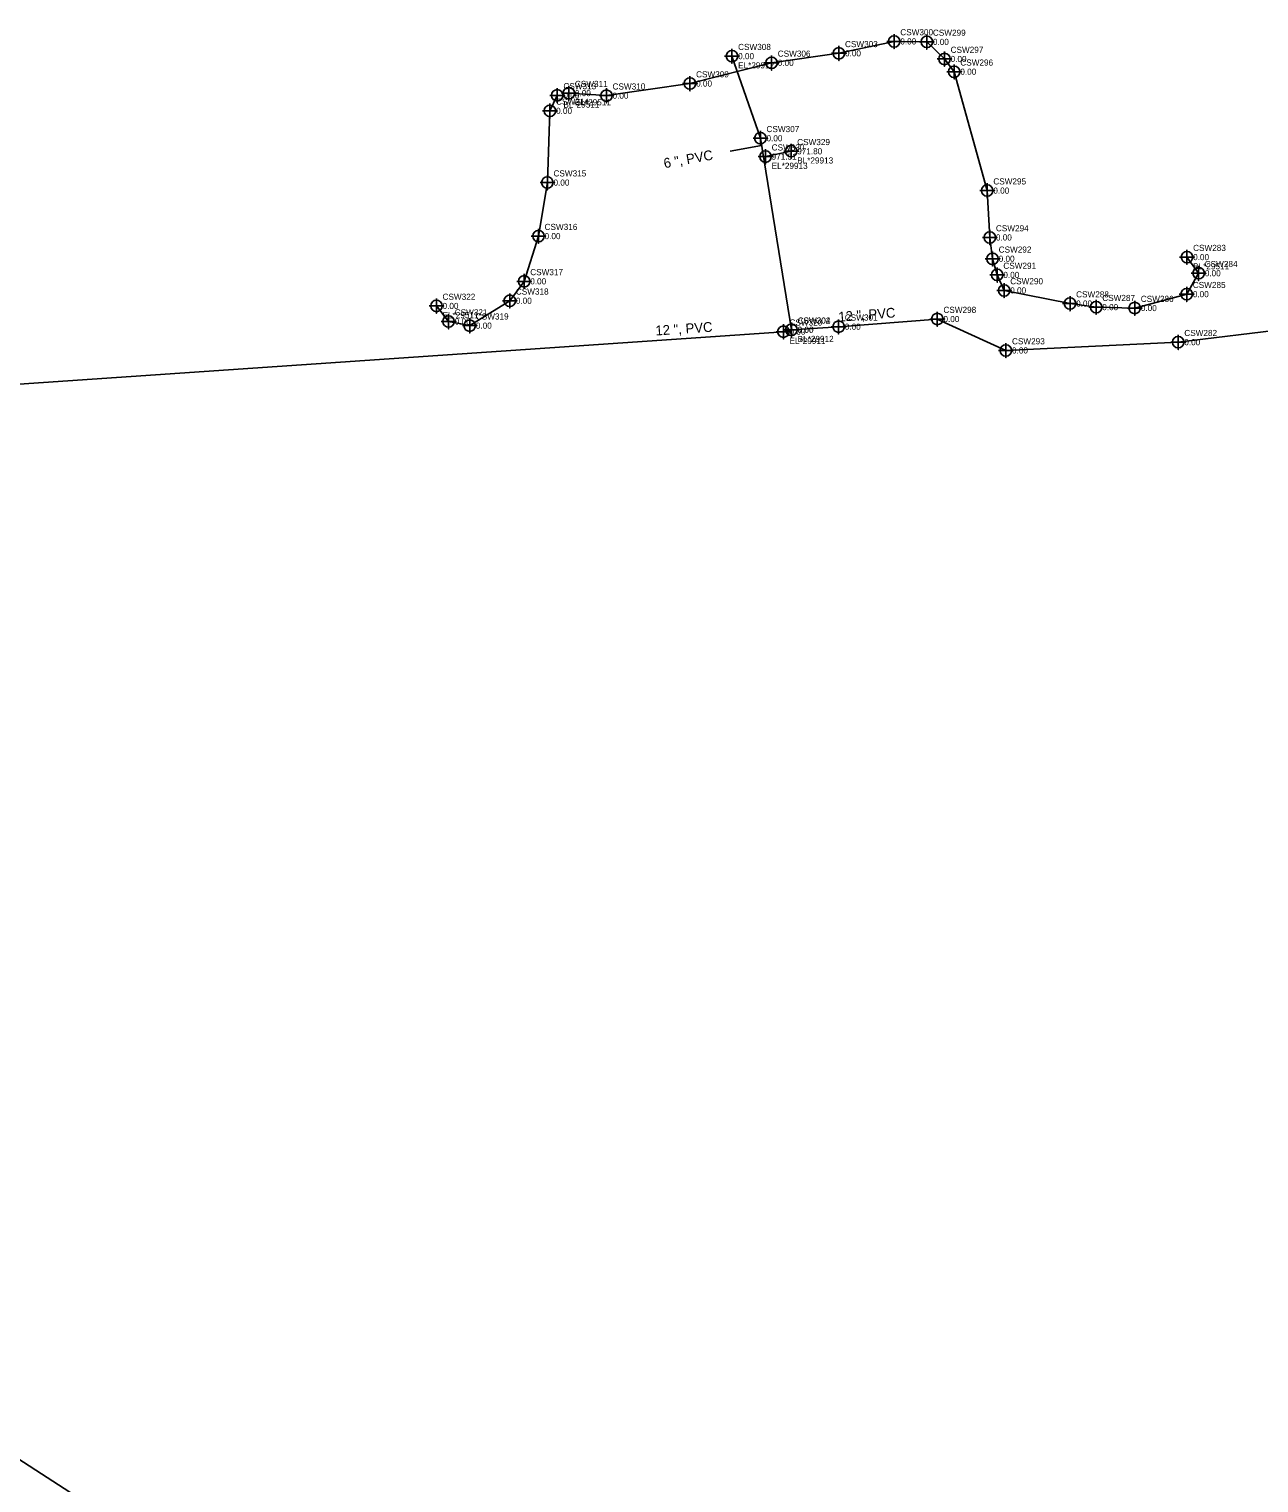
# Model space of a CAD drawing. Extents: x 1182504 to 1186036, y 573002 to 575111.
# Drawn here: x 1183993 to 1184495, y 573983 to 574577 of the extents above; entities that cross this region are included whole.
import ezdxf

# ---------------------------------------------------------------- set-up
doc = ezdxf.new("R2010")
doc.units = 0
for name, color, linetype in [('Exist Utilities Power UG Cable SUE LOS B', 7, 'Continuous'), ('Exist Utilities Power UG Cable SUE LOS B Cogo Comment', 7, 'Continuous'), ('Exist Utilities Power UG Cable SUE LOS B Cogo Elevation', 7, 'Continuous'), ('Exist Utilities Power UG Cable SUE LOS B Cogo Number', 7, 'Continuous'), ('Exist Utilities Power UG Cable SUE LOS B Cogo Point CELL', 7, 'Continuous'), ('Exist Utilities Telephone UG Conduit SUE LOS B', 7, 'Continuous'), ('Exist Utilities Water UG Line SUE LOS B', 7, 'Continuous'), ('Exist Utilities Water UG Line SUE LOS B Cogo Comment', 7, 'Continuous'), ('Exist Utilities Water UG Line SUE LOS B Cogo Elevation', 7, 'Continuous'), ('Exist Utilities Water UG Line SUE LOS B Cogo Number', 7, 'Continuous'), ('Exist Utilities Water UG Line SUE LOS B Cogo Point CELL', 7, 'Continuous'), ('Exist Utilities Water UG Line SUE LOS B Leader', 7, 'Continuous'), ('Exist Utilities Water UG Line SUE LOS B Text', 7, 'Continuous'), ('Exist Utilities Water UG Line SUE LOS C', 7, 'Continuous'), ('Exist Utilities Water UG Line SUE LOS C Text', 7, 'Continuous')]:
    doc.layers.add(name, color=color, linetype=linetype)

msp = doc.modelspace()

# ---------------------------------------------------------------- linework, layer by layer
at = {"layer": 'Exist Utilities Power UG Cable SUE LOS B'}
for points in [[(1184213.38, 574550.48), (1184228.73, 574549.44), (1184262.82, 574554.39), (1184296.14, 574562.84), (1184323.59, 574566.73), (1184346.15, 574571.57), (1184359.46, 574571.38), (1184366.68, 574564.41), (1184370.65, 574559.2), (1184384.11, 574510.71), (1184385.17, 574491.59), (1184386.29, 574482.88), (1184388.2, 574476.3), (1184391.01, 574469.98), (1184417.9, 574464.62), (1184428.57, 574463.15), (1184444.3, 574462.79), (1184465.51, 574468.45), (1184470.39, 574477), (1184465.64, 574483.57)], [(1184208.68, 574549.56), (1184205.69, 574543.24), (1184204.64, 574513.97), (1184201, 574492.14), (1184195.15, 574473.68), (1184189.28, 574465.77), (1184172.95, 574455.6), (1184164.33, 574457.3), (1184159.37, 574463.64)]]:
    msp.add_lwpolyline(points, dxfattribs=at)
at = {"layer": 'Exist Utilities Power UG Cable SUE LOS B Cogo Point CELL'}
for points in [[(1184346.15, 574574.57), (1184346.15, 574568.57), (1184346.15, 574571.57), (1184349.15, 574571.57), (1184343.15, 574571.57)], [(1184359.46, 574574.38), (1184359.46, 574568.38), (1184359.46, 574571.38), (1184362.46, 574571.38), (1184356.46, 574571.38)], [(1184296.14, 574565.84), (1184296.14, 574559.84), (1184296.14, 574562.84), (1184299.14, 574562.84), (1184293.14, 574562.84)], [(1184323.59, 574569.73), (1184323.59, 574563.73), (1184323.59, 574566.73), (1184326.59, 574566.73), (1184320.59, 574566.73)], [(1184366.68, 574567.41), (1184366.68, 574561.41), (1184366.68, 574564.41), (1184369.68, 574564.41), (1184363.68, 574564.41)], [(1184370.65, 574562.2), (1184370.65, 574556.2), (1184370.65, 574559.2), (1184373.65, 574559.2), (1184367.65, 574559.2)], [(1184262.82, 574557.39), (1184262.82, 574551.39), (1184262.82, 574554.39), (1184265.82, 574554.39), (1184259.82, 574554.39)], [(1184208.68, 574552.56), (1184208.68, 574546.56), (1184208.68, 574549.56), (1184211.68, 574549.56), (1184205.68, 574549.56)], [(1184213.38, 574553.48), (1184213.38, 574547.48), (1184213.38, 574550.48), (1184216.38, 574550.48), (1184210.38, 574550.48)], [(1184228.73, 574552.44), (1184228.73, 574546.44), (1184228.73, 574549.44), (1184231.73, 574549.44), (1184225.73, 574549.44)], [(1184205.69, 574546.24), (1184205.69, 574540.24), (1184205.69, 574543.24), (1184208.69, 574543.24), (1184202.69, 574543.24)], [(1184204.64, 574516.97), (1184204.64, 574510.97), (1184204.64, 574513.97), (1184207.64, 574513.97), (1184201.64, 574513.97)], [(1184384.11, 574513.71), (1184384.11, 574507.71), (1184384.11, 574510.71), (1184387.11, 574510.71), (1184381.11, 574510.71)], [(1184201, 574495.14), (1184201, 574489.14), (1184201, 574492.14), (1184204, 574492.14), (1184198, 574492.14)], [(1184385.17, 574494.59), (1184385.17, 574488.59), (1184385.17, 574491.59), (1184388.17, 574491.59), (1184382.17, 574491.59)], [(1184386.29, 574485.88), (1184386.29, 574479.88), (1184386.29, 574482.88), (1184389.29, 574482.88), (1184383.29, 574482.88)], [(1184465.64, 574486.57), (1184465.64, 574480.57), (1184465.64, 574483.57), (1184468.64, 574483.57), (1184462.64, 574483.57)], [(1184195.15, 574476.68), (1184195.15, 574470.68), (1184195.15, 574473.68), (1184198.15, 574473.68), (1184192.15, 574473.68)], [(1184388.2, 574479.3), (1184388.2, 574473.3), (1184388.2, 574476.3), (1184391.2, 574476.3), (1184385.2, 574476.3)], [(1184470.39, 574480), (1184470.39, 574474), (1184470.39, 574477), (1184473.39, 574477), (1184467.39, 574477)], [(1184391.01, 574472.98), (1184391.01, 574466.98), (1184391.01, 574469.98), (1184394.01, 574469.98), (1184388.01, 574469.98)], [(1184465.51, 574471.45), (1184465.51, 574465.45), (1184465.51, 574468.45), (1184468.51, 574468.45), (1184462.51, 574468.45)], [(1184159.37, 574466.64), (1184159.37, 574460.64), (1184159.37, 574463.64), (1184162.37, 574463.64), (1184156.37, 574463.64)], [(1184189.28, 574468.77), (1184189.28, 574462.77), (1184189.28, 574465.77), (1184192.28, 574465.77), (1184186.28, 574465.77)], [(1184417.9, 574467.62), (1184417.9, 574461.62), (1184417.9, 574464.62), (1184420.9, 574464.62), (1184414.9, 574464.62)], [(1184428.57, 574466.15), (1184428.57, 574460.15), (1184428.57, 574463.15), (1184431.57, 574463.15), (1184425.57, 574463.15)], [(1184444.3, 574465.79), (1184444.3, 574459.79), (1184444.3, 574462.79), (1184447.3, 574462.79), (1184441.3, 574462.79)], [(1184164.33, 574460.3), (1184164.33, 574454.3), (1184164.33, 574457.3), (1184167.33, 574457.3), (1184161.33, 574457.3)], [(1184172.95, 574458.6), (1184172.95, 574452.6), (1184172.95, 574455.6), (1184175.95, 574455.6), (1184169.95, 574455.6)]]:
    msp.add_lwpolyline(points, dxfattribs=at)
for centre in [(1184346.15, 574571.57), (1184359.46, 574571.38), (1184323.59, 574566.73), (1184366.68, 574564.41), (1184296.14, 574562.84), (1184370.65, 574559.2), (1184262.82, 574554.39), (1184208.68, 574549.56), (1184213.38, 574550.48), (1184228.73, 574549.44), (1184205.69, 574543.24), (1184204.64, 574513.97), (1184384.11, 574510.71), (1184201, 574492.14), (1184385.17, 574491.59), (1184386.29, 574482.88), (1184465.64, 574483.57), (1184388.2, 574476.3), (1184470.39, 574477), (1184195.15, 574473.68), (1184391.01, 574469.98), (1184465.51, 574468.45), (1184159.37, 574463.64), (1184189.28, 574465.77), (1184417.9, 574464.62), (1184428.57, 574463.15), (1184444.3, 574462.79), (1184164.33, 574457.3), (1184172.95, 574455.6)]:
    msp.add_circle(centre, 2.34, dxfattribs=at)
at = {"layer": 'Exist Utilities Telephone UG Conduit SUE LOS B'}
msp.add_lwpolyline([(1183461.9, 574217.61), (1183507.97, 574205.1), (1183555.78, 574190.97), (1183600.29, 574174.7), (1183642.38, 574158.78), (1183685.83, 574141.54), (1183729.44, 574124.53), (1183772.61, 574105.48), (1183815.48, 574084.72), (1183856.9, 574064.89), (1183910.26, 574040.72), (1183938.65, 574025.64), (1184017.13, 573974.93), (1184056.25, 573949.51), (1184095.95, 573918.75), (1184120.25, 573896.12), (1184153.18, 573876.37), (1184177.6, 573863.32)], dxfattribs=at)
at = {"layer": 'Exist Utilities Water UG Line SUE LOS B'}
msp.add_line((1184304.08, 574526.76), (1184293.66, 574524.57), dxfattribs=at)
for points in [[(1184304.28, 574453.94), (1184291.56, 574532.06), (1184279.97, 574565.57)], [(1184300.95, 574453.14), (1184304.21, 574453.9), (1184323.5, 574455.17), (1184363.75, 574458.3), (1184391.73, 574445.48), (1184462.04, 574448.86), (1184506.81, 574454.35), (1184555.01, 574455.54), (1184598.54, 574456.3), (1184658.94, 574457.22), (1184678.28, 574456.14), (1184698.37, 574456.58)]]:
    msp.add_lwpolyline(points, dxfattribs=at)
at = {"layer": 'Exist Utilities Water UG Line SUE LOS B Cogo Point CELL'}
for points in [[(1184279.97, 574568.57), (1184279.97, 574562.57), (1184279.97, 574565.57), (1184282.97, 574565.57), (1184276.97, 574565.57)], [(1184291.56, 574535.06), (1184291.56, 574529.06), (1184291.56, 574532.06), (1184294.56, 574532.06), (1184288.56, 574532.06)], [(1184293.66, 574527.57), (1184293.66, 574521.57), (1184293.66, 574524.57), (1184296.66, 574524.57), (1184290.66, 574524.57)], [(1184304.08, 574529.76), (1184304.08, 574523.76), (1184304.08, 574526.76), (1184307.08, 574526.76), (1184301.08, 574526.76)], [(1184363.75, 574461.3), (1184363.75, 574455.3), (1184363.75, 574458.3), (1184366.75, 574458.3), (1184360.75, 574458.3)], [(1184300.95, 574456.14), (1184300.95, 574450.14), (1184300.95, 574453.14), (1184303.95, 574453.14), (1184297.95, 574453.14)], [(1184304.21, 574456.9), (1184304.21, 574450.9), (1184304.21, 574453.9), (1184307.21, 574453.9), (1184301.21, 574453.9)], [(1184304.28, 574456.94), (1184304.28, 574450.94), (1184304.28, 574453.94), (1184307.28, 574453.94), (1184301.28, 574453.94)], [(1184323.5, 574458.17), (1184323.5, 574452.17), (1184323.5, 574455.17), (1184326.5, 574455.17), (1184320.5, 574455.17)], [(1184391.73, 574448.48), (1184391.73, 574442.48), (1184391.73, 574445.48), (1184394.73, 574445.48), (1184388.73, 574445.48)], [(1184462.04, 574451.86), (1184462.04, 574445.86), (1184462.04, 574448.86), (1184465.04, 574448.86), (1184459.04, 574448.86)]]:
    msp.add_lwpolyline(points, dxfattribs=at)
for centre in [(1184279.97, 574565.57), (1184291.56, 574532.06), (1184293.66, 574524.57), (1184304.08, 574526.76), (1184363.75, 574458.3), (1184300.95, 574453.14), (1184304.21, 574453.9), (1184304.28, 574453.94), (1184323.5, 574455.17), (1184391.73, 574445.48), (1184462.04, 574448.86)]:
    msp.add_circle(centre, 2.34, dxfattribs=at)
at = {"layer": 'Exist Utilities Water UG Line SUE LOS B Leader'}
msp.add_line((1184292.04, 574529.11), (1184279.21, 574526.81), dxfattribs=at)
at = {"layer": 'Exist Utilities Water UG Line SUE LOS C'}
msp.add_lwpolyline([(1183675.77, 574460.48), (1183882.99, 574425.76), (1183989.16, 574431.68), (1184300.95, 574453.14)], dxfattribs=at)

# ---------------------------------------------------------------- texts
at = {"layer": 'Exist Utilities Power UG Cable SUE LOS B Cogo Comment'}
for s, p in [('EL*29511', (1184215.88, 574545.48)), ('BL*29511', (1184211.18, 574544.56)), ('BL*29511', (1184468.14, 574478.57)), ('EL*29511', (1184161.87, 574458.64))]:
    msp.add_text(s, height=2.5, dxfattribs=at).set_placement(p)
at = {"layer": 'Exist Utilities Power UG Cable SUE LOS B Cogo Elevation'}
for p in [(1184348.65, 574570.32), (1184361.96, 574570.13), (1184326.09, 574565.48), (1184369.18, 574563.16), (1184298.64, 574561.59), (1184373.15, 574557.95), (1184265.32, 574553.14), (1184211.18, 574548.31), (1184215.88, 574549.23), (1184231.23, 574548.19), (1184208.19, 574541.99), (1184207.14, 574512.72), (1184386.61, 574509.46), (1184203.5, 574490.89), (1184387.67, 574490.34), (1184388.79, 574481.63), (1184468.14, 574482.32), (1184390.7, 574475.05), (1184472.89, 574475.75), (1184197.65, 574472.43), (1184393.51, 574468.73), (1184161.87, 574462.39), (1184191.78, 574464.52), (1184420.4, 574463.37), (1184468.01, 574467.2), (1184431.07, 574461.9), (1184446.8, 574461.54), (1184166.83, 574456.05), (1184175.45, 574454.35)]:
    msp.add_text('0.00', height=2.5, dxfattribs=at).set_placement(p)
at = {"layer": 'Exist Utilities Power UG Cable SUE LOS B Cogo Number'}
for s, p in [('CSW303', (1184326.09, 574569.23)), ('CSW300', (1184348.65, 574574.07)), ('CSW299', (1184361.96, 574573.88)), ('CSW306', (1184298.64, 574565.34)), ('CSW297', (1184369.18, 574566.91)), ('CSW296', (1184373.15, 574561.7)), ('CSW313', (1184211.18, 574552.06)), ('CSW311', (1184215.88, 574552.98)), ('CSW310', (1184231.23, 574551.94)), ('CSW309', (1184265.32, 574556.89)), ('CSW314', (1184208.19, 574545.74)), ('CSW315', (1184207.14, 574516.47)), ('CSW295', (1184386.61, 574513.21)), ('CSW316', (1184203.5, 574494.64)), ('CSW294', (1184387.67, 574494.09)), ('CSW283', (1184468.14, 574486.07)), ('CSW292', (1184388.79, 574485.38)), ('CSW317', (1184197.65, 574476.18)), ('CSW291', (1184390.7, 574478.8)), ('CSW284', (1184472.89, 574479.5)), ('CSW318', (1184191.78, 574468.27)), ('CSW290', (1184393.51, 574472.48)), ('CSW285', (1184468.01, 574470.95)), ('CSW322', (1184161.87, 574466.14)), ('CSW288', (1184420.4, 574467.12)), ('CSW287', (1184431.07, 574465.65)), ('CSW286', (1184446.8, 574465.29)), ('CSW321', (1184166.83, 574459.8)), ('CSW319', (1184175.45, 574458.1))]:
    msp.add_text(s, height=2.5, dxfattribs=at).set_placement(p)
at = {"layer": 'Exist Utilities Water UG Line SUE LOS B Cogo Comment'}
for s, p in [('EL*29912', (1184282.47, 574560.57)), ('BL*29913', (1184306.58, 574521.76)), ('EL*29913', (1184296.16, 574519.57)), ('EL*29911', (1184303.45, 574448.14)), ('BL*29912', (1184306.78, 574448.94))]:
    msp.add_text(s, height=2.5, dxfattribs=at).set_placement(p)
at = {"layer": 'Exist Utilities Water UG Line SUE LOS B Cogo Elevation'}
for s, p in [('0.00', (1184282.47, 574564.32)), ('0.00', (1184294.06, 574530.81)), ('971.51', (1184296.16, 574523.32)), ('971.80', (1184306.58, 574525.51)), ('0.00', (1184366.25, 574457.05)), ('0.00', (1184303.45, 574451.89)), ('0.00', (1184306.71, 574452.65)), ('0.00', (1184306.78, 574452.69)), ('0.00', (1184326, 574453.92)), ('0.00', (1184464.54, 574447.61)), ('0.00', (1184394.23, 574444.23))]:
    msp.add_text(s, height=2.5, dxfattribs=at).set_placement(p)
at = {"layer": 'Exist Utilities Water UG Line SUE LOS B Cogo Number'}
for s, p in [('CSW308', (1184282.47, 574568.07)), ('CSW307', (1184294.06, 574534.56)), ('CSW329', (1184306.58, 574529.26)), ('CSW330', (1184296.16, 574527.07)), ('CSW302', (1184306.71, 574456.4)), ('CSW304', (1184306.78, 574456.44)), ('CSW301', (1184326, 574457.67)), ('CSW298', (1184366.25, 574460.8)), ('CSW320', (1184303.45, 574455.64)), ('CSW282', (1184464.54, 574451.36)), ('CSW293', (1184394.23, 574447.98))]:
    msp.add_text(s, height=2.5, dxfattribs=at).set_placement(p)
at = {"layer": 'Exist Utilities Water UG Line SUE LOS B Text'}
for s, rotation, p in [('6 ", PVC', 10.15261, (1184252.47, 574519.83)), ('12 ", PVC', 4.44136, (1184323.54, 574457.18))]:
    msp.add_text(s, height=4, rotation=rotation, dxfattribs=at).set_placement(p)
at = {"layer": 'Exist Utilities Water UG Line SUE LOS C Text'}
msp.add_text('12 ", PVC', height=4, rotation=3.93753, dxfattribs=at).set_placement((1184248.88, 574451.56))

doc.saveas('drawing.dxf')
